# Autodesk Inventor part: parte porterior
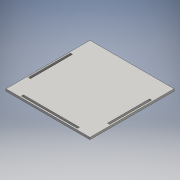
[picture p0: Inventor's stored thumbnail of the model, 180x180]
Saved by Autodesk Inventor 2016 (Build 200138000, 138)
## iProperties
Created: 2016-06
Part Number: parte porterior
Material: Genérico
Document SubType Name: Modeling
Designer: adm
Density: 1 g/cm^3
Appearance: Valor por defecto
Author: adm
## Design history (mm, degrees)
sketch "Boceto1"
  geometry: 1 further point
sketch "Boceto2"
  geometry: L1 (-60, -60)-(60, -60); L2 (60, -60)-(60, 60); L3 (60, 60)-(-60, 60); L4 (-60, 60)-(-60, -60); L5 (-60, -60)-(60, 60); L6 (60, -60)-(-60, 60); L7 (58, 30)-(58, -30); L8 (-58, -30)-(-58, 30); L9 (-55, 30)-(-55, -30); L10 (-58, -30)-(-55, -30); L11 (-58, 30)-(-55, 30); L12 (55, 30)-(58, 30); L13 (55, -30)-(58, -30); L14 (55, 30)-(55, -30); 1 further point
  constraints: 28 end point, 3 parallel, 2 midpoint, 2 perpendicular, 1 horizontal, 1 vertical
  dimensions: "d0" = 120 distance of L3.end L2.end; "d1" = 120 distance of L2.end L1.end; "d2" = 2 distance between parallel lines of L2 L7
extrude "Extrusión1" new body sketch "Boceto2" distance "d7" = 3; taper "d8" = 0 deg
sketch "Boceto3"
  geometry: L1 (-60, -60)-(60, -60) reference; L2 (-40, -58)-(40, -58); L3 (-40, -55)-(40, -55); L4 (0, -55)-(0, -60); L5 (-40, -55)-(-40, -58); L6 (40, -55)-(40, -58); 1 further point
  constraints: 10 end point, 3 parallel, 2 midpoint, 1 vertical
  dimensions: "d10" = 3 distance between parallel lines of L2 L3; "d11" = 40 distance between parallel lines of L4 L5; "d12" = 40 distance between parallel lines of L6 L4
extrude "Extrusión2" cut sketch "Boceto3" distance "d13" = 10; taper "d14" = 0 deg
node "Sólido1"
other parameters: "d3" = 3, "d4" = 3
